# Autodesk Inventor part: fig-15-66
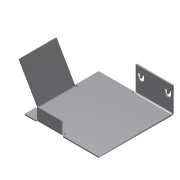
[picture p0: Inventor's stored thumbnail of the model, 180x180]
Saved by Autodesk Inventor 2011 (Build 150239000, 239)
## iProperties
Shininess: 77.0
Angle Display Precision: 2
Document Length Units: 11269
Document Angle Units: 11279
Document Time Units: 11290
Document Mass Units: 11283
Document Length Units Precision: 3
Document Angle Units Precision: 2
Created: 2002-04
Part Number: fig-15-66
Document SubType Name: Sheet Metal
Density: 1 g/cm^3
Sheet Metal Rule: Default
Density: 0.0
Volumn: 0.0
Area: 0.0
PropertySet Name: Model Information
Control State: 0
Master: False
Checked Out: False
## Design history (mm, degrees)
node "Face1"
  sketch "Sketch1"
    geometry: L1 (12.647, 25.882)-(12.647, -14.118); L2 (12.647, -14.118)-(-17.353, -14.118); L3 (-17.353, -14.118)-(-17.353, 15.882); L4 (-17.353, 15.882)-(-2.353, 15.882); L5 (-2.353, 15.882)-(-2.353, 25.882); L6 (-2.353, 25.882)-(12.647, 25.882); 1 further point
    constraints: 12 end point, 4 parallel, 1 perpendicular
    dimensions: "d5" = 30 distance of L2.end L3.end; "d6" = 10 distance of L4.end L5.end; "d7" = 15 distance of L3.end L4.end; "d25" = 15 distance of L5.end L1.start
sketch "Sketch3"
  geometry: L1 (10, -15)-(10, 0)
  constraints: 2 end point
feature "Fold3" sketch "Sketch3" dims "d26" = 0.5 (= BendRadius), "d27" = 90 deg, "d28" = 0.5 (= BendRadius), "d96" = 0.5 (= BendReliefWidth), "d97" = 0.25 (= BendReliefDepth), "d98" = 1 (= MinimumRemnant), "SeamGap" = 0.01, "Thickness" = 0.5
node "Flange2"
sketch "Sketch6"
  geometry: L1 (-6.914, 3.413)-(-5.843, 3.413); L2 (-5.843, 0.624)-(-6.914, 0.624); L3 (-6.914, 2.432)-(-5.843, 2.432); L4 (-5.843, 1.605)-(-6.914, 1.605); L5 (-6.914, 0.624)-(-6.914, 1.605); L6 (-6.914, 2.432)-(-6.914, 3.413); L7 (-6.914, 12.568)-(-6.914, 11.587); L8 (-6.914, 14.376)-(-6.914, 13.395); L9 (-6.914, 11.587)-(-5.843, 11.587); L10 (-5.843, 14.376)-(-6.914, 14.376); L11 (-6.914, 12.568)-(-5.843, 12.568); L12 (-5.843, 13.395)-(-6.914, 13.395); A1 r 1.394 centre (-5.843, 2.018) between (-5.843, 0.624) and (-5.843, 3.413); A2 r 0.413 centre (-5.843, 2.018) between (-5.843, 1.605) and (-5.843, 2.432); A3 r 1.394 centre (-5.843, 12.982) between (-5.843, 11.587) and (-5.843, 14.376); A4 r 0.413 centre (-5.843, 12.982) between (-5.843, 12.568) and (-5.843, 13.395)
  constraints: 24 end point, 8 point on circle, 4 centre point, 3 equal length, 1 perpendicular
cut "Cut1" sketch "Sketch6" dims "d49" = 0.5 (= Thickness), "d50" = 0
node "Flange3"
body "Solid1"
face "Plate1" dims "Thickness" = 0.5
sketch "Sketch5"
  geometry: L1 (20, 0)-(5, 0); L2 (5, 0)-(5, 15); L3 (5, 15)-(20, 15); L4 (20, 15)-(20, 0)
  constraints: 8 end point
face "Plate6" dims "d35" = 10, "d36" = 5, "d38" = 15, "d39" = 60 deg, "d40" = 0.5 (= BendRadius), "Thickness" = 0.5, "MinimumRemnant" = 1 (= 2 x Thickness), "BendReliefWidth" = 0.5 (= Thickness)
bend "Bend5" dims "d38" = 15, "d39" = 60 deg, "d40" = 0.5 (= BendRadius), "d99" = 0.5 (= BendReliefWidth), "d100" = 0.25 (= BendReliefDepth), "d101" = 1 (= MinimumRemnant), "SeamGap" = 0.01, "Thickness" = 0.5, "MinimumRemnant" = 1 (= 2 x Thickness), "BendReliefWidth" = 0.5 (= Thickness), "TransitionRadius" = 0.5 (= BendRadius)
sketch "Sketch7"
  geometry: L1 (25, 0)-(15, 0); L2 (15, 0)-(15, 5); L3 (15, 5)-(25, 5); L4 (25, 5)-(25, 0)
  constraints: 8 end point
face "Plate7" dims "d57" = 5, "d58" = 10, "d60" = 5, "d61" = 90 deg, "d62" = 0.5 (= BendRadius), "Thickness" = 0.5, "MinimumRemnant" = 1 (= 2 x Thickness), "BendReliefWidth" = 0.5 (= Thickness)
bend "Bend7" dims "d59" = 0.5 (= BendRadius), "d60" = 5, "d61" = 90 deg, "d62" = 0.5 (= BendRadius), "d102" = 0.5 (= BendReliefWidth), "d103" = 0.25 (= BendReliefDepth), "d104" = 1 (= MinimumRemnant), "SeamGap" = 0.01, "Thickness" = 0.5, "MinimumRemnant" = 1 (= 2 x Thickness), "BendReliefWidth" = 0.5 (= Thickness)
other parameters: "BendRadius" = 0.5 (= Thickness), "BendReliefDepth" = 0.25 (= 0.5 x Thickness), "CornerReliefSize" = 2 (= 4 x Thickness), "d0" = 0.5 (= BendRadius), "d13" = 0.5 (= BendRadius), "d31" = 0.5 (= BendRadius), "d37" = 0.5 (= BendRadius), "JacobiRadiusSize" = 0.5 (= Thickness), "GapSize" = 0.5 (= Thickness)
